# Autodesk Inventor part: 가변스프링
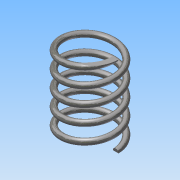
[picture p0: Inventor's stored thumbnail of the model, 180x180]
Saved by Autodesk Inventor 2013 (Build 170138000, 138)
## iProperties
Created: 2018-12
Part Number: 가변스프링
Material: 스테인리스강
Document SubType Name: Modeling
Designer: Administrator
Mass: 7.07026 g
Surface Area: 17.7415 cm^2
Volume: 0.875032 cm^3
Density: 8.08 g/cm^3
Author: Administrator
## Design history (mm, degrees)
sketch "스케치1"
  geometry: L1 (0, 0)-(9, 0); L2 (9, 0)-(9, 28.5); L3 (9, 28.5)-(0, 28.5); L4 (0, 28.5)-(0, 0); C1 r 1 at (9, 0)
  constraints: 8 end point, 2 parallel, 1 centre point, 1 coincident, 1 horizontal, 1 perpendicular
  dimensions: "d0" = 18 diameter of L2 L4; "d2" = 28.49994 distance of L1.end L2.end (derived); "d3" = 2 diameter of C1
feature "코일1" sketch "스케치1" pitch "d4" = 10; turns "d6" = 5; dims "d5" = 28.49994 (= d2), "d7" = 0, angle "d8" = 90 deg, angle "d9" = 90 deg, "d10" = 0, "d11" = 0
sketch "스케치2"
  geometry: C1 r 16.085 at (0, 0); 1 further point
  constraints: 1 centre point, 1 coincident
extrude "돌출1" sketch "스케치2" distance "d12" = 28.49994 (= d2); taper "d13" = 0 deg
node "솔리드1"
